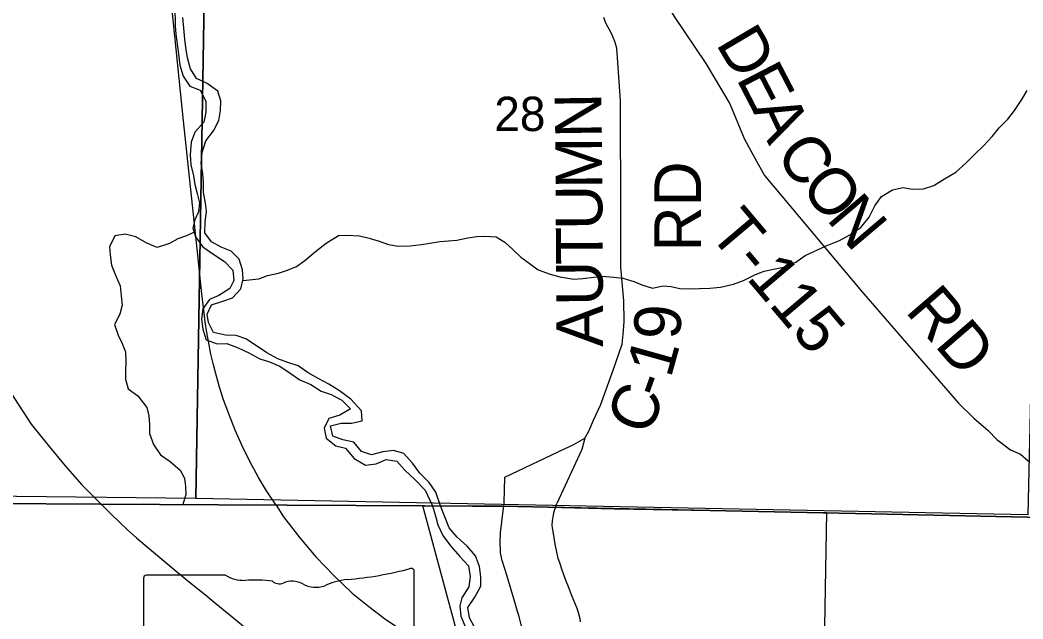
# Model space of a CAD drawing. Extents: x -7.1 to 34, y 0 to 22.
# Drawn here: x 4.468 to 5.689, y 17.646 to 18.375 of the extents above; entities that cross this region are included whole.
import ezdxf

# ---------------------------------------------------------------- set-up
doc = ezdxf.new("R2010")
doc.units = 0
for name, color, linetype in [('GM_X_City_Street', 7, 'Continuous'), ('GM_X_Corporation', 7, 'Continuous'), ('GM_X_County_Road', 7, 'Continuous'), ('GM_X_County_Road_Text', 7, 'Continuous'), ('GM_X_Major_River', 7, 'Continuous'), ('GM_X_Minor_River', 7, 'Continuous'), ('GM_X_Rail_Line', 7, 'Continuous'), ('GM_X_Section', 7, 'Continuous'), ('GM_X_Section_Text', 7, 'Continuous'), ('GM_X_State_Route', 7, 'Continuous'), ('GM_X_State_Shield', 7, 'Continuous'), ('GM_X_Township_Road', 7, 'Continuous'), ('GM_X_Township_Road_Text', 7, 'Continuous'), ('SH_Cut_Line', 7, 'Continuous')]:
    doc.layers.add(name, color=color, linetype=linetype)

msp = doc.modelspace()

# ---------------------------------------------------------------- linework, layer by layer
at = {"layer": 'GM_X_City_Street'}
for points in [[(5.0797, 17.6324), (5.0751, 17.6501), (5.0737, 17.6547), (5.0703, 17.6661), (5.0659, 17.6811), (5.0604, 17.6989), (5.0551, 17.7168), (5.0547, 17.7185), (5.053, 17.7261), (5.0527, 17.7289), (5.0523, 17.738), (5.0527, 17.7505), (5.0544, 17.764), (5.0574, 17.7871)], [(5.1505, 17.6424), (5.1497, 17.6458), (5.1474, 17.6548), (5.1462, 17.6585), (5.1403, 17.6729), (5.1356, 17.6848), (5.1322, 17.6937), (5.1275, 17.7062), (5.1258, 17.7115), (5.125, 17.714), (5.1233, 17.7195), (5.1222, 17.7235), (5.1196, 17.7367), (5.1186, 17.7422), (5.1162, 17.7571), (5.1159, 17.7597), (5.1161, 17.7657), (5.1165, 17.7676), (5.1174, 17.7726), (5.1183, 17.7765), (5.1194, 17.7804), (5.1207, 17.7841), (5.1215, 17.7862)]]:
    msp.add_lwpolyline(points, dxfattribs=at)
at = {"layer": 'GM_X_Corporation'}
msp.add_lwpolyline([(5.0125, 17.582), (4.9582, 17.7835), (5.0789, 17.7827), (5.1918, 17.78), (5.4498, 17.7755), (5.4449, 17.4981)], dxfattribs=at)
at = {"layer": 'GM_X_County_Road'}
msp.add_lwpolyline([(5.0574, 17.7871), (5.0583, 17.8183), (5.1316, 17.8533), (5.1415, 17.8577), (5.1555, 17.8658), (5.1604, 17.8746), (5.166, 17.8877), (5.1745, 17.9061), (5.19, 17.9487), (5.2011, 17.9803), (5.2027, 17.9965), (5.2036, 18.0085), (5.2032, 18.0332), (5.1995, 18.0742), (5.1995, 18.1337), (5.1989, 18.2767), (5.1945, 18.3409), (5.1922, 18.3491), (5.1884, 18.3578), (5.1852, 18.3639), (5.1819, 18.3695), (5.1799, 18.3746), (5.1786, 18.3781)], dxfattribs=at)
at = {"layer": 'GM_X_Major_River'}
msp.add_line((4.97, 17.7833), (4.98, 17.7833), dxfattribs=at)
for points in [[(4.6564, 18.3906), (4.6567, 18.3682), (4.6573, 18.358), (4.6607, 18.3338), (4.6625, 18.3201), (4.6665, 18.3069), (4.6747, 18.2945), (4.6873, 18.2898), (4.694, 18.2762), (4.6942, 18.263), (4.6917, 18.2508), (4.6805, 18.2384), (4.6762, 18.2262), (4.6749, 18.211), (4.6759, 18.1989), (4.6791, 18.1853), (4.6808, 18.1747), (4.6833, 18.1637), (4.6861, 18.1524), (4.6852, 18.1417), (4.6808, 18.1318), (4.6783, 18.1222), (4.6815, 18.1109), (4.6904, 18.0989), (4.7027, 18.0904), (4.7169, 18.0811), (4.727, 18.0703), (4.728, 18.0578), (4.7232, 18.0482), (4.71, 18.0396), (4.6983, 18.0349), (4.6905, 18.0234), (4.6888, 18.0108), (4.6905, 17.9987), (4.6946, 17.9855), (4.7079, 17.9808), (4.7197, 17.9813), (4.7335, 17.9759), (4.7465, 17.97), (4.7599, 17.9627), (4.7714, 17.9587), (4.784, 17.9536), (4.7967, 17.945), (4.8086, 17.9369), (4.8217, 17.9314), (4.8343, 17.9233), (4.8466, 17.9189), (4.8596, 17.9123), (4.87, 17.9015), (4.8572, 17.8937), (4.8436, 17.89), (4.8381, 17.8782), (4.8406, 17.8657), (4.8525, 17.8564), (4.864, 17.8539), (4.8748, 17.8412), (4.8886, 17.8331), (4.9015, 17.8348), (4.9136, 17.8399), (4.9266, 17.8379), (4.9363, 17.827), (4.949, 17.8151), (4.961, 17.8024), (4.97, 17.7833)], [(4.98, 17.7833), (4.9743, 17.8003), (4.9662, 17.812), (4.9546, 17.8232), (4.9456, 17.8355), (4.9352, 17.8471), (4.9226, 17.8507), (4.9097, 17.8494), (4.8957, 17.8457), (4.8834, 17.8497), (4.8741, 17.8609), (4.8608, 17.8637), (4.8485, 17.8685), (4.846, 17.881), (4.8589, 17.8842), (4.8715, 17.884), (4.8843, 17.8869), (4.8834, 17.899), (4.8706, 17.9132), (4.8568, 17.9236), (4.8437, 17.9318), (4.8318, 17.938), (4.8188, 17.9454), (4.8065, 17.9539), (4.7938, 17.9579), (4.7816, 17.9623), (4.7682, 17.97), (4.7559, 17.9782), (4.7428, 17.9867), (4.731, 17.991), (4.718, 17.9912), (4.7035, 17.9944), (4.6973, 18.0068), (4.6956, 18.017), (4.7011, 18.0281), (4.7147, 18.0329), (4.7264, 18.0369), (4.7365, 18.0477), (4.7393, 18.0599), (4.7388, 18.0709), (4.7344, 18.0837), (4.7247, 18.0938), (4.7125, 18.0985), (4.701, 18.1048), (4.6928, 18.116), (4.693, 18.1289), (4.6947, 18.1423), (4.6937, 18.1521), (4.6912, 18.1654), (4.691, 18.1771), (4.6905, 18.1877), (4.6884, 18.2006), (4.6897, 18.2139), (4.694, 18.228), (4.7033, 18.2403), (4.71, 18.2526), (4.7117, 18.2651), (4.7122, 18.2769), (4.7086, 18.2886), (4.6955, 18.2979), (4.6825, 18.3038), (4.6755, 18.3158), (4.6715, 18.329), (4.6697, 18.3415), (4.6684, 18.3517), (4.6674, 18.3654), (4.6661, 18.3783)], [(4.97, 17.7833), (4.9741, 17.7698), (4.9766, 17.7605), (4.9825, 17.7473), (4.9918, 17.7349), (5.0034, 17.7218), (5.0137, 17.7102), (5.0158, 17.6973), (5.0144, 17.6847), (5.0059, 17.6713), (5.0033, 17.6618), (5.0046, 17.6489), (5.0097, 17.6365)], [(5.0211, 17.6355), (5.0153, 17.6472), (5.0132, 17.6597), (5.0218, 17.6723), (5.0289, 17.6857), (5.0291, 17.6971), (5.0274, 17.7096), (5.0223, 17.7224), (5.0123, 17.7344), (5, 17.7453), (4.9904, 17.7566), (4.98, 17.7833)]]:
    msp.add_lwpolyline(points, dxfattribs=at)
at = {"layer": 'GM_X_Minor_River'}
for points in [[(4.7389, 18.0581), (4.7587, 18.0599), (4.7693, 18.0638), (4.7826, 18.067), (4.7936, 18.0705), (4.8045, 18.0751), (4.8144, 18.0821), (4.8276, 18.0932), (4.8404, 18.1032), (4.8555, 18.1128), (4.8654, 18.1132), (4.881, 18.1122), (4.8928, 18.1093), (4.9049, 18.106), (4.9164, 18.1019), (4.9282, 18.0997), (4.943, 18.1002), (4.9566, 18.1019), (4.9669, 18.1035), (4.979, 18.1055), (4.9896, 18.1063), (4.9995, 18.1072), (5.0132, 18.1099), (5.0242, 18.1115), (5.0336, 18.112), (5.0477, 18.111), (5.058, 18.1046), (5.068, 18.0956), (5.0775, 18.0862), (5.0879, 18.0791), (5.0986, 18.0708), (5.1134, 18.0656), (5.1252, 18.0623), (5.142, 18.0594), (5.1533, 18.0603), (5.1666, 18.0619), (5.1761, 18.0631), (5.1909, 18.0621), (5.202, 18.0607), (5.2153, 18.0566), (5.2252, 18.0525), (5.2378, 18.0484), (5.2507, 18.0516), (5.2609, 18.0505), (5.2712, 18.0483), (5.2845, 18.0477), (5.2951, 18.0482), (5.308, 18.0487), (5.3209, 18.0499), (5.3365, 18.0534), (5.349, 18.0581), (5.3633, 18.0651), (5.3739, 18.0693), (5.3853, 18.0717), (5.3994, 18.0745), (5.4126, 18.0803), (5.4239, 18.0884), (5.4338, 18.093), (5.4493, 18.1), (5.4656, 18.1065), (5.4784, 18.1135), (5.4916, 18.1223), (5.5018, 18.1349), (5.5089, 18.1487), (5.5168, 18.1601), (5.5304, 18.1682), (5.5433, 18.171), (5.5543, 18.1692), (5.568, 18.1697), (5.5808, 18.1736), (5.5937, 18.1817), (5.6073, 18.1897), (5.6201, 18.2012), (5.6303, 18.2112), (5.6412, 18.2219), (5.6517, 18.2334), (5.6604, 18.2437), (5.6706, 18.2544), (5.6788, 18.2651), (5.6878, 18.2785), (5.6942, 18.2892)], [(4.6798, 18.1169), (4.6705, 18.1123), (4.6599, 18.1085), (4.6497, 18.1031), (4.6349, 18.098), (4.622, 18.1032), (4.6086, 18.1111), (4.5957, 18.1144), (4.5832, 18.1124), (4.5768, 18.099), (4.5773, 18.0892), (4.5793, 18.0766), (4.584, 18.0645), (4.5898, 18.0513), (4.591, 18.0392), (4.5919, 18.0278), (4.5893, 18.0167), (4.5826, 18.0042), (4.5872, 17.9913), (4.5923, 17.9811), (4.5961, 17.9709), (4.5966, 17.9591), (4.596, 17.9473), (4.596, 17.9378), (4.5996, 17.9261), (4.611, 17.9175), (4.6222, 17.9031), (4.6245, 17.8929), (4.6254, 17.8827), (4.6255, 17.8717), (4.6301, 17.858), (4.6386, 17.8456), (4.6504, 17.8373), (4.6627, 17.8268), (4.6681, 17.817), (4.6693, 17.8071), (4.6698, 17.7973), (4.666, 17.7849)]]:
    msp.add_lwpolyline(points, dxfattribs=at)
at = {"layer": 'GM_X_Rail_Line'}
for points in [[(4.7797, 17.7841), (4.7677, 17.8016), (4.7581, 17.818), (4.7471, 17.8384), (4.7381, 17.8566), (4.7297, 17.8756), (4.7219, 17.8954), (4.7157, 17.9125), (4.7107, 17.9281), (4.7069, 17.9413), (4.7033, 17.9553), (4.7001, 17.9683), (4.6977, 17.9815), (4.6952, 17.9945), (4.6932, 18.0077), (4.6914, 18.0217), (4.6891, 18.0416), (4.6866, 18.0647), (4.6842, 18.0888), (4.667, 18.2522), (4.6527, 18.3912)], [(4.7797, 17.7841), (4.7887, 17.7702), (4.8084, 17.7445), (4.8279, 17.7214), (4.8498, 17.6985), (4.8724, 17.6772), (4.8925, 17.661), (4.9118, 17.6462), (4.9381, 17.6282), (5.026, 17.5721), (5.1985, 17.4631), (5.2605, 17.423), (5.3035, 17.396), (5.3421, 17.3708), (5.3729, 17.3495), (5.423, 17.3098), (5.4733, 17.2706), (5.5024, 17.2494)]]:
    msp.add_lwpolyline(points, dxfattribs=at)
at = {"layer": 'GM_X_Section'}
for points in [[(3.8597, 18.828), (4.6987, 18.8125), (4.6817, 17.7925), (3.8439, 17.8017), (3.8583, 18.7127)], [(4.6987, 18.8125), (5.7181, 18.7951), (5.6951, 17.7726), (4.6817, 17.7925)]]:
    msp.add_lwpolyline(points, close=True, dxfattribs=at)
at = {"layer": 'GM_X_State_Route'}
msp.add_line((4.6777, 17.6878), (4.6821, 17.6841), dxfattribs=at)
for points in [[(4.4452, 17.9387), (4.4811, 17.883), (4.5014, 17.8579), (4.5227, 17.8322), (4.5431, 17.8092), (4.5577, 17.7944)], [(4.5577, 17.7944), (4.5684, 17.7834), (4.5782, 17.7736), (4.5895, 17.7628), (4.5991, 17.7538), (4.6096, 17.7446), (4.62, 17.7355), (4.6556, 17.7058), (4.6722, 17.6922), (4.6777, 17.6878)], [(4.6821, 17.6841), (4.6934, 17.675), (4.7041, 17.6662)], [(4.7041, 17.6662), (4.7215, 17.6519), (4.7374, 17.6388), (4.7488, 17.6294)]]:
    msp.add_lwpolyline(points, dxfattribs=at)
at = {"layer": 'GM_X_State_Shield'}
for p, q in [((4.718, 17.699), (4.6214, 17.699)), ((4.9478, 17.5993), (4.9478, 17.704)), ((4.6182, 17.6956), (4.6182, 17.4955))]:
    msp.add_line(p, q, dxfattribs=at)
for centre, major_axis, start_param, end_param in [((4.622, 17.696), (0.00382, 0), 1.712693, 3.28349), ((4.741, 17.7223), (0.037, 0), 4.042523, 4.731795), ((4.8304, 17.9719), (0.3495, 0), 4.814394, 5.042369), ((4.9441, 17.7044), (0.00367, 0), 6.141152, 7.989035), ((4.7532, 17.5867), (0.133, 0), 1.404758, 1.657858), ((4.7834, 17.6971), (0.0107, 0), 3.836095, 5.185415), ((4.7991, 17.6739), (0.0222, 0), 0.950623, 2.079405), ((4.8278, 17.7056), (0.0267, 0), 4.081561, 5.145723), ((4.875, 17.6379), (0.0703, 0), 1.699011, 2.107814)]:
    msp.add_ellipse(centre, major_axis=major_axis, ratio=0.8, start_param=start_param, end_param=end_param, dxfattribs=at)
at = {"layer": 'GM_X_Township_Road'}
for points in [[(3.0659, 17.6986), (3.7215, 17.6707), (3.8238, 17.6717), (3.8304, 17.7952), (4.3, 17.7873), (4.5657, 17.7857), (4.7094, 17.7848), (5.0443, 17.7832), (5.0544, 17.7831), (5.1115, 17.7819), (5.5047, 17.7737), (5.7514, 17.7685), (6.1904, 17.7592), (6.3575, 17.7557), (6.7118, 17.7486), (6.7254, 18.1319), (6.7433, 18.7732), (6.7479, 19.0295), (6.7613, 19.7723), (6.7882, 20.743), (6.7921, 20.9), (2.1, 20.9)], [(5.2365, 18.4256), (5.2644, 18.3793), (5.303, 18.3221), (5.3322, 18.273), (5.3497, 18.2309), (5.3626, 18.2069), (5.3746, 18.1857), (5.4925, 18.0448), (5.6107, 17.9087), (5.6293, 17.8901), (5.6466, 17.8752), (5.6574, 17.8644), (5.6741, 17.8518), (5.6861, 17.8465), (5.6957, 17.8381), (5.7094, 17.8273), (5.7516, 17.7679)], [(5.1555, 17.8658), (5.1519, 17.8519), (5.1215, 17.7862)], [(6.7058, 17.2839), (6.7118, 17.7486), (6.3575, 17.7557), (6.1904, 17.7592), (5.7514, 17.7685), (5.5047, 17.7737), (5.1115, 17.7819), (5.0544, 17.7831), (5.0443, 17.7832), (4.7094, 17.7848), (4.5657, 17.7857), (4.3, 17.7873), (3.8304, 17.7952), (3.8238, 17.6717), (3.7215, 17.6707), (3.0659, 17.6986), (2.7886, 17.7105), (2.5551, 17.7155), (2.1, 17.7253), (2.1, 14.1)]]:
    msp.add_lwpolyline(points, dxfattribs=at)
at = {"layer": 'SH_Cut_Line'}
for points in [[(8.9, 17.7079), (8.9, 20.9), (2.1, 20.9), (2.1, 17.7253), (2.5551, 17.7155), (2.7886, 17.7105), (3.0659, 17.6986), (3.7215, 17.6707), (3.8238, 17.6717), (3.8304, 17.7952), (4.3, 17.7873), (4.5657, 17.7857), (4.7094, 17.7848), (5.0443, 17.7832), (5.0544, 17.7831), (5.1115, 17.7819), (5.5047, 17.7737), (5.7514, 17.7685), (6.1904, 17.7592), (6.3575, 17.7557), (6.7118, 17.7486), (7.7202, 17.7285), (8.4472, 17.7189), (8.6668, 17.7136)], [(2.1, 17.7253), (2.1, 14.1), (8.9, 14.1), (8.9, 17.7079), (8.6668, 17.7136), (8.4472, 17.7189), (7.7202, 17.7285), (6.7118, 17.7486), (6.3575, 17.7557), (6.1904, 17.7592), (5.7514, 17.7685), (5.5047, 17.7737), (5.1115, 17.7819), (5.0544, 17.7831), (5.0443, 17.7832), (4.7094, 17.7848), (4.5657, 17.7857), (4.3, 17.7873), (3.8304, 17.7952), (3.8238, 17.6717), (3.7215, 17.6707), (3.0659, 17.6986), (2.7886, 17.7105), (2.5551, 17.7155)]]:
    msp.add_lwpolyline(points, close=True, dxfattribs=at)

# ---------------------------------------------------------------- texts
at = {"layer": 'GM_X_County_Road_Text'}
for s, height, rotation, p in [('N', 0.0568, 90.8927, (5.1764, 18.2319)), ('M', 0.0568, 90.3293, (5.1768, 18.1697)), ('RD', 0.05682, 90, (5.2971, 18.0932)), ('U', 0.0568, 90.3169, (5.1771, 18.1196)), ('T', 0.0568, 90.3229, (5.1773, 18.0771)), ('U', 0.0568, 90.3169, (5.1776, 18.0271)), ('A', 0.0568, 90.3206, (5.1779, 17.9771)), ('9', 0.0568, 87.3888, (5.2717, 17.9852)), ('1', 0.0568, 74.3673, (5.2601, 17.9378)), ('C', 0.0568, 68.5626, (5.2334, 17.867)), ('-', 0.0568, 70.3299, (5.251, 17.9119))]:
    msp.add_text(s, height=height, rotation=rotation, dxfattribs=at).set_placement(p)
at = {"layer": 'GM_X_Section_Text'}
msp.add_text('28', height=0.04186, rotation=0, dxfattribs=at).set_placement((5.0453, 18.2399))
at = {"layer": 'GM_X_Township_Road_Text'}
for s, height, rotation, p in [('D', 0.0568, 300.5596, (5.3144, 18.3465)), ('E', 0.0568, 297.4074, (5.3394, 18.3041)), ('A', 0.0568, 295.2486, (5.3587, 18.2669)), ('C', 0.0568, 306.4909, (5.3863, 18.2113)), ('O', 0.0568, 310.2263, (5.4165, 18.1706)), ('N', 0.0568, 310.2369, (5.4488, 18.1324)), ('T-115', 0.05682, 310.2363, (5.305, 18.1153)), ('RD', 0.05682, 310.8148, (5.5447, 18.0203))]:
    msp.add_text(s, height=height, rotation=rotation, dxfattribs=at).set_placement(p)

doc.saveas('drawing.dxf')
